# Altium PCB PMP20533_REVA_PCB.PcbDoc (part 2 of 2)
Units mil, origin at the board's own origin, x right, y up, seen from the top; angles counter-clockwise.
Board outline 2795.47 x 1881.89 mil, 4 copper layers (Top Layer, Signal Layer 1, Signal Layer 2, Bottom Layer), stack 40.634 mil thick; 90 components, 59 nets, 312 pads, 73 vias.
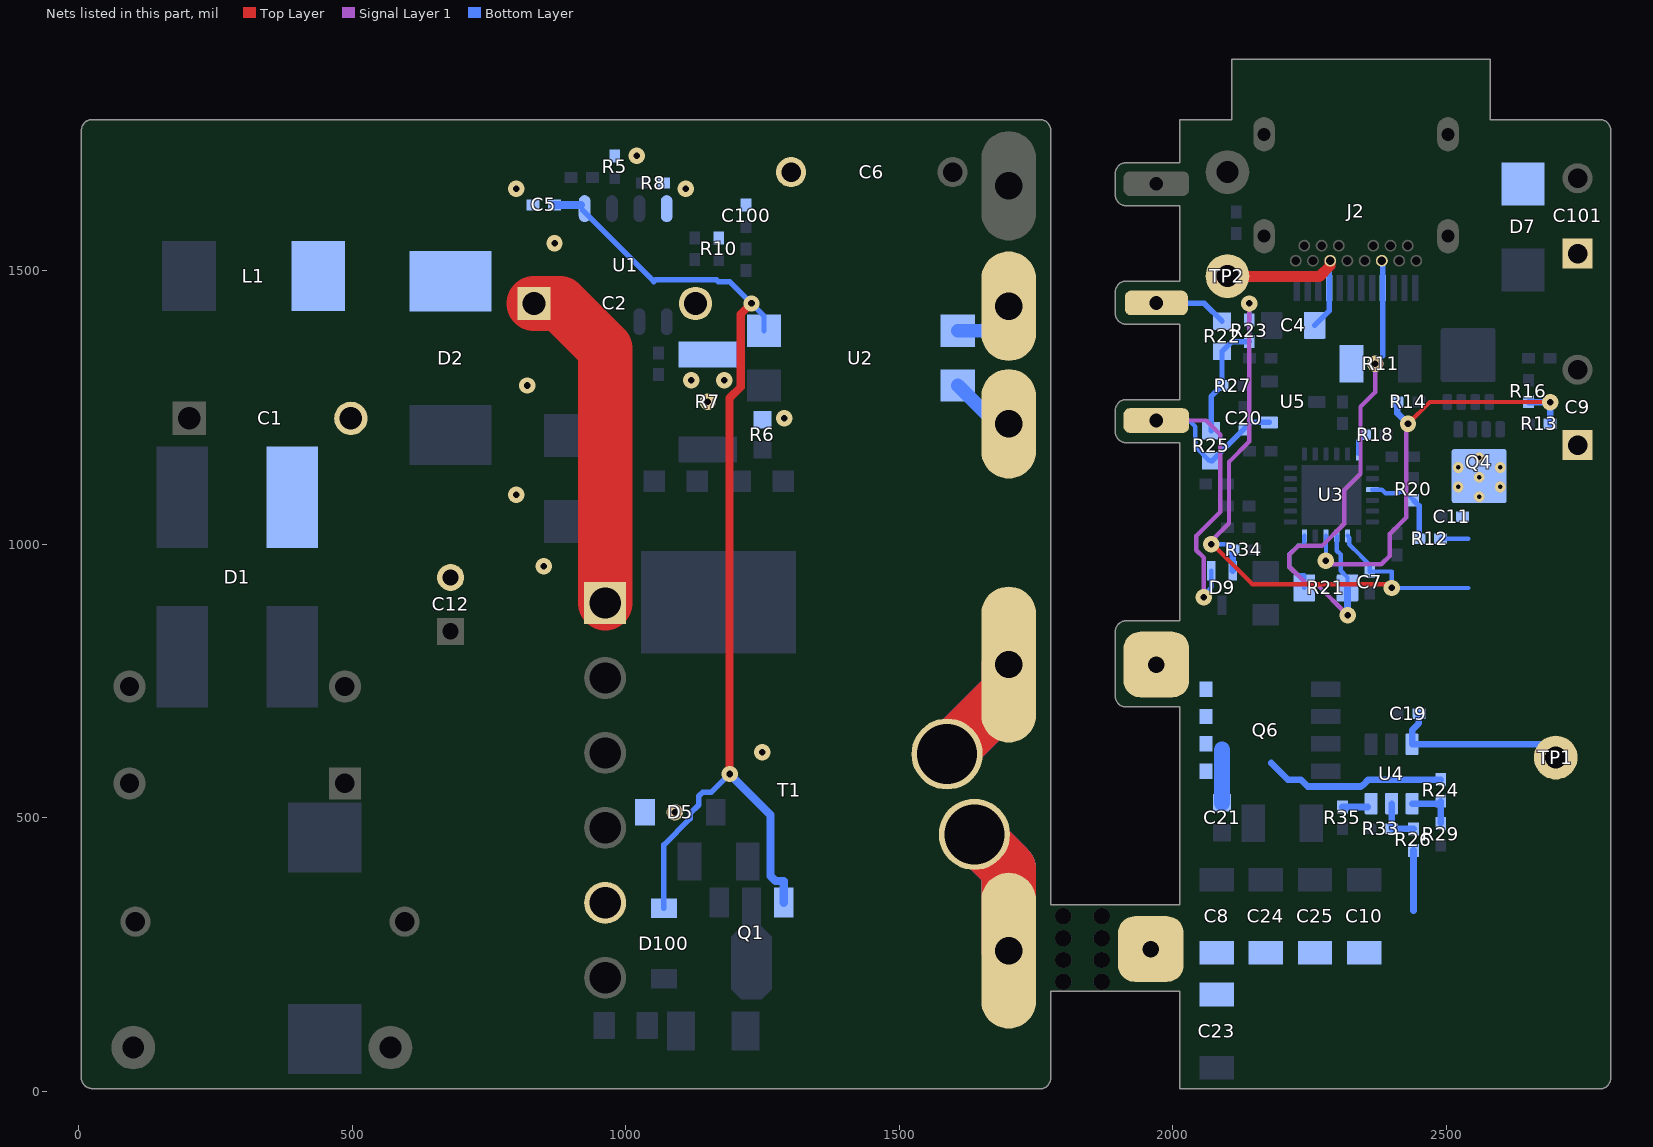
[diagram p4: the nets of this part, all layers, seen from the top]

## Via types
v1: diameter 30, hole 12, Top Layer to Bottom Layer, 54 vias
v2: diameter 19.68, hole 7.87, Top Layer to Bottom Layer, 17 vias
v3: diameter 19.68, hole 7.87, Top Layer to Bottom Layer, tented both sides, 2 vias

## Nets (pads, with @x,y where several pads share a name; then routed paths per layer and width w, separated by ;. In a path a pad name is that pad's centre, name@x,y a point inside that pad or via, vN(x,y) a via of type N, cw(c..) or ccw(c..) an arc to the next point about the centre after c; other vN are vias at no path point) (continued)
NetR12_2: R12.2 R20.2 U3.15 | length 150.4
  Bottom Layer w8: U3.15@2364.8,1099.84 2382.15,1099.84 2388.87,1093.13 2411.13,1093.13 2414.13,1096.13 2424.19,1096.13 R20.2@2440,1080.31
  Bottom Layer w10: R20.2@2440,1080.31 2450.31,1070 2450.31,1020
NetR13_2: R13.2 R14.2 R16.1 U3.22 | length 829
  Top Layer w8: v1(2430,1220) 2469.96,1259.96 v1@2689.41,1259.96
  Signal Layer 1 w8: v1(2280,970) 2286.87,963.13 2381.13,963.13 2396.87,978.87 2396.87,1018.87 2426.87,1048.87 2426.87,1216.87 v1(2430,1220)
  Bottom Layer w8: v1@2280.16,970.16 U3.22@2280.16,1015.2
  Bottom Layer w12: R14.2@2410.31,1260 2410.31,1239.69 v1(2430,1220) ; R16.1@2650.63,1259.69 v1(2689.69,1259.69) R13.2@2689.69,1220
NetR18_2: R18.2 U3.12 | length 39.8
  Bottom Layer w8: U3.12@2339.21,1164.8 2339.21,1188.9 R18.2@2350.31,1200
NetR21_1: R21.1 U3.24 | length 131.8
  Bottom Layer w8: R21.1@2240.63,920 2240.63,943.13 2228.87,943.13 2213.13,958.87 2213.13,981.13 2228.87,996.87 2240.63,996.87 2240.63,1015.04 U3.24@2240.79,1015.2
NetR22_2: R22.2 R23.1 R25.1 R27.2 | length 210.4
  Bottom Layer w10: R25.1@2070,1207.56 2070,1269.69 R27.2@2090.31,1290 ; R27.2@2090,1290.31 R22.2@2090,1352.44 2107.87,1370.32 R23.1@2140,1370.32
NetR24_1: R24.1 R29.2 U4.1 | length 95.1
  Bottom Layer w12: U4.1@2437.4,525.87 2485.55,525.87 R24.1@2490,530.32 R29.2@2490,489.69
NetR26_1: R26.1 R33.2 U4.2 | length 86.2
  Bottom Layer w12: U4.2@2400,525.87 2400,479.68 R26.1@2440,479.68
NetR35_2: R35.2 U4.3 | length 46.4
  Bottom Layer w12: R35.2@2310,519.69 U4.3@2356.42,519.69
PGND: C1.2 C2.2 C5.2 C6.2 C12.2 C100.2 D1.4 D5.2 R5.1 R6.1 R7.1 R8.1 R10.1 T1.5 U1.4
  other v1: 1090,510 1250,620 850,960 800,1090 1290,1230 1150,1260 820,1290 1120,1300 1180,1300 870,1550 800,1650 1110,1650 1020,1710
VBUS: C4.1 D7.1 J2.A4 J2.A9 J2.B4 J2.B9 R11.1 R21.2 TP2.1 U3.21 | length 1262.8
  Top Layer w20: TP2.1@2100,1490 2100,1489.37 2268.14,1489.37 2287.75,1508.98 J2.B9@2287.75,1518.07
  Signal Layer 1 w8: v1(2320,870) 2262.75,927.25 2244.74,927.25 2213.13,958.87 2213.13,981.13 2228.87,996.87 2272.86,996.87 2313.56,1037.57 2313.56,1099 2343.13,1128.56 2343.13,1251.13 2370,1278.01 v1(2370,1330)
  Bottom Layer w8: U3.21@2299.84,1015.2 2299.84,988.16 2306.87,981.13 2306.87,951.67 2319.37,939.17 R21.2@2319.37,920
  Bottom Layer w10: C4.1@2259.37,1400 2285.78,1426.41 J2.A4@2285.78,1468.47 J2.B9@2285.78,1516.1 ; 2384.21,1344.21 J2.A9@2384.21,1468.47 J2.B4@2384.21,1516.1
  Bottom Layer w12: v1@2319.37,870.63 R21.2@2319.37,920
VDC: C2.1 D2.2 L1.2 T1.1 U1.8 | length 668.6
  Top Layer w100: C2.1@832.36,1440 880,1440 962.5,1357.5 T1.1@962.5,892.5
  Bottom Layer w10: 885.71,1406.65 U1.8@925,1406.65
VDD: C5.1 D100.2 Q1.3 U1.1 U2.4 | length 1956
  Top Layer w15: v1(1190,580) 1190,1267.04 1210.37,1287.42 1210.37,1420.37 v1(1230,1440)
  Bottom Layer w10: U1.1@921.65,1610 1051.65,1480 1055.04,1483.39 1165.61,1483.39 1168.99,1480 1190,1480 v1(1230,1440) 1252.83,1417.17 U2.4@1252.83,1390 ; D100.2@1070,334.47 1070,450.58 1117.87,498.45 1117.87,507.87 1133.58,523.58 1133.58,539.35 1141.12,546.89 1156.89,546.89 v1(1190,580)
  Bottom Layer w15: C5.1@869.68,1620 U1.1@918.35,1620 ; v1(1190,580) 1264.63,505.37 1264.63,393.63 1273.63,384.63 1289.06,384.63 Q1.3@1289.06,344.8
VOPTO_1: pad.0@1700,1435 U2.1 | length 111.5
  Bottom Layer w25: U2.1@1607.17,1390 1655,1390 pad.0@1700,1435
VOPTO_1B: pad.2@1970,1441 R22.1 | length 132.4
  Bottom Layer w10: pad.2@1971,1440 2057.56,1440 R22.1@2090,1407.56
VOPTO_2: pad.0@1700,1220 U2.2 | length 121.8
  Bottom Layer w25: U2.2@1607.17,1290 1677.17,1220 pad.0@1700,1220
VOPTO_2B: C20.1 D9.1 pad.2@1970,1226 R25.2 U5.1 | length 790
  Signal Layer 1 w8: pad.2@1970,1226 2061.24,1226 2086.87,1200.37 2086.87,1058.87 2043.13,1015.12 2043.13,988.87 2056.54,975.46 v1(2056.54,903.27)
  Bottom Layer w8: pad.2@1970,1226 2029.84,1226 2041.39,1214.45 2041.39,1177.69 2066.64,1152.44 R25.2@2070,1152.44 ; v1(2056.54,903.27) 2056.54,906.54 2070.32,920.32 D9.1@2070.32,951.5
  Bottom Layer w10: R25.2@2070,1152.44 2072.13,1152.44 C20.1@2130,1210.32 2142.28,1222.6 U5.1@2176.69,1222.6
VOUT_UNFILT: pad.0@1700,257 T1.A | length 476.8
  Top Layer w100: T1.A@1637.5,469.5 1700,407 pad.0@1700,257
  Bottom Layer w100: T1.A@1637.5,469.5 1700,407 pad.0@1700,257
VOUT_UNFILTB: C7.1 C8.1 C9.1 C10.1 C11.1 C19.1 C23.1 C24.1 C25.1 C101.1 D9.2 pad.2@1960,260 Q4.5 Q4.6 Q4.7 Q4.8 Q4.9@2560,1124.41 R12.1 R23.2 R26.2 R34.1 TP1.1 U3.20 U4.6 | length 1729.5
  Top Layer w8: v1@2072.41,1000 2145.54,926.87 2393.13,926.87 v1(2400,920)
  Signal Layer 1 w8: v1(2070,1000) 2070,1005.59 2102.81,1038.4 2102.81,1150.45 2140,1187.64 v1(2140,1440)
  Bottom Layer w8: v1(2070,1000) 2100.32,1000 R34.1@2110.32,990 ; R23.2@2140,1409.69 v1(2140,1440) ; U3.20@2319.53,1015.2 2322.61,1012.11 2322.61,999.63 2343.13,979.12 2343.13,978.87 2358.87,963.13 2360,963.13 C7.1@2360,950 ; C7.1@2360,949.68 C7.1@2360,950 ; R12.1@2489.68,1010 2540,1010 ; 2540,920 v1(2400,920) 2400,950 C7.1@2360,950
  Bottom Layer w12: D9.2@2109.69,951.5 R34.1@2109.69,989.37 ; 2440,330 R26.2@2440,440.31 ; C19.1@2449.68,690 2449.68,672.36 2437.4,660.08 U4.6@2437.4,634.13 2675.87,634.13 TP1.1@2700,610
  other v2: 2521.61,1104.72 2598.39,1104.72 2560,1122.54 2521.61,1140.35 2598.39,1140.35 2560,1158.17
  other v3: 2560,1086.91
VSR_DRAIN: pad.0@1700,780 T1.B | length 420.2
  Top Layer w100: T1.B@1587.5,616.5 1700,729 pad.0@1700,780
  Bottom Layer w100: T1.B@1587.5,616.5 1700,729 pad.0@1700,780
VSR_DRAINB: C21.2 pad.2@1970,780 Q6.5 Q6.6 Q6.7 Q6.8 R24.2 | length 429.5
  Bottom Layer w12: 2180,600 2210.31,569.69 2234.01,569.69 2246.55,557.15 2343.94,557.15 2346.22,559.43 2347.53,559.43 2357.79,569.69 R24.2@2490,569.69
  Bottom Layer w30: C21.2@2090,527.56 2090,624.15
pads on no net: J2.A2 J2.A3 J2.A8 J2.A10 J2.A11 J2.B2 J2.B3 J2.B8 J2.B10 J2.B11 Q4.9@2521.61,1103.74 Q4.9@2533.92,1123.86 Q4.9@2533.92,1158.35 Q4.9@2547.2,1103.74 Q4.9@2560,1137.11 Q4.9@2572.8,1103.74 Q4.9@2586.08,1123.86 Q4.9@2586.08,1158.35 Q4.9@2598.39,1103.74 Q5.9@2501.61,1366.26 Q5.9@2513.92,1311.65 Q5.9@2513.92,1346.14 Q5.9@2527.2,1366.26 Q5.9@2540,1332.89 Q5.9@2552.8,1366.26 Q5.9@2566.08,1311.65 Q5.9@2566.08,1346.14 Q5.9@2578.39,1366.26 T1.2 T1.4 U3.9 U3.10 U3.11 U3.25@2261.85,1061.85 U3.25@2261.85,1118.15 U3.25@2318.15,1061.85 U3.25@2318.15,1118.15

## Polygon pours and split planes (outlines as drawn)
GND on Bottom Layer "BOTTOM_LAYER_GND_P050" (solid, remove dead copper, pour order 50): 1900,1891.31 1900,0 2805.49,0 2805.49,1891.31
VBUS on Bottom Layer "BOTTOM_LAYER_VBUS_P020" (solid, remove dead copper, pour order 20): 2690,1710 2690,1560 2601.02,1560 2601.02,1290 2238.26,1290 2238.26,1710
NetQ5_5 on Bottom Layer "BOTTOM_LAYER_NETQ5_5_P018" (solid, remove dead copper, pour order 18): 2400,1400 2400,1290 2601.02,1290 2601.02,1400
NetQ4_1 on Bottom Layer "BOTTOM_LAYER_NETQ4_1_P016" (solid, remove dead copper, pour order 16): 2606.93,1280 2606.93,1200 2510,1200 2510,1280
VSR_DRAINB on Bottom Layer "BOTTOM_LAYER_VSR_DRAINB_P014" (solid, remove dead copper, pour order 14): 2250,840.24 1910,840.24 1910,550 2250,550
VOUT_UNFILTB on Bottom Layer "BOTTOM_LAYER_VOUT_UNFILTB_P012" (solid, remove dead copper, pour order 12): 2510,1220 2510,4.41 2805.49,4.41 2805.49,1220
VOUT_UNFILTB on Bottom Layer "BOTTOM_LAYER_VOUT_UNFILTB_P010" (solid, remove dead copper, pour order 10): 1900,340 1900,4.41 2530,4.41 2530,340
PGND on Bottom Layer "BOTTOM_LAYER_PGND_P006" (solid, remove dead copper, pour order 6): 0.18,1776.06 0.18,990 650,990 650,900 832.46,900 831.97,4.41 1340,4.41 1340,1776.06
VDC on Bottom Layer "BOTTOM_LAYER_VDC_P004" (solid, remove dead copper, pour order 4): 340,1610 340,1350 890,1350 890,1480 787.58,1480 787.58,1610
NetQ2_2 on Bottom Layer "BOTTOM_LAYER_NETQ2_2_P002" (solid, remove dead copper, pour order 2): 1030,1080 1320,1080 1320,1200 1030,1200
NetD3_2 on Bottom Layer "BOTTOM_LAYER_NETD3_2_P000" (solid, remove dead copper, pour order 0): 1030,1062.5 1030,690 1327.47,690 1327.47,1062.5
GND on Top Layer "TOP_LAYER_GND_P058" (solid, remove dead copper, pour order 58): 1889.95,1886.3 1889.95,4.41 2805.49,4.41 2805.49,1886.3
PGND on Top Layer "TOP_LAYER_PGND_P008" (solid, remove dead copper, pour order 8): 0.18,1776.06 0.18,990 650,990 650,900 832.5,900 832.5,9.42 1340,9.42 1340,1776.06
GND on Signal Layer 2 "SIGNAL_LAYER_2_GND_P052" (solid, remove dead copper, pour order 52): 1900,1886.3 1900,4.41 2799.83,4.41 2799.83,1886.3
GND on Signal Layer 1 "SIGNAL_LAYER_1_GND_P056" (solid, remove dead copper, pour order 56): 1889.95,1886.3 1889.95,9.42 2805.49,9.42 2805.49,1886.3
VSR_DRAINB on Signal Layer 1 "SIGNAL_LAYER_1_VSR_DRAINB_P034" (solid, remove dead copper, pour order 34): 1897.47,859.92 1897.47,710 2018.09,710 2018.09,859.92
VOUT_UNFILTB on Signal Layer 1 "SIGNAL_LAYER_1_VOUT_UNFILTB_P054" (solid, remove dead copper, pour order 54): 2800.47,1070 2502.13,1070 2502.13,1570 2800.47,1570

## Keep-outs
Keep-Out Layer:
  rectangle: 1280,400 1500,766.06
  rectangle: 1340,730 1560,1776.06
  rectangle: 1340,10 1560,520
  lines w5: 2.5,25 ccw(c25,25) 25,2.5 ; 2.5,25 ccw(c5,25) 2.5,25 ; 2.5,25 ccw(c5,25) 2.5,25 ; 2.5,25 2.7,1756.38 ; 2.7,1756.38 cw(c24.88,1756.38) 24.88,1778.56 ; 2.7,1756.38 ccw(c24.88,1756.38) 2.7,1756.38 ; 2.7,1756.38 2.7,1756.38 ; 24.9,1778.56 ccw(c24.88,1776.06) 24.88,1778.56 ; 24.9,1778.56 ccw(c24.88,1776.06) 24.88,1778.56 ; 24.88,1778.56 24.9,1778.56 ; 24.9,1778.56 1757.14,1778.56 ; 25,2.5 ccw(c25,25) 25,2.5 ; 25,2.5 25,2.5 ; 25,2.5 1757.16,1.91 ; 1757.16,1.91 ccw(c1757.17,4.41) 1757.17,1.91 ; 1757.16,1.91 ccw(c1757.17,4.41) 1757.17,1.91 ; 1757.17,1.91 ccw(c1757.17,24.09) 1779.35,24.09 1779.35,180.65 2010.57,180.65 2010.57,4.41 ; 1757.17,1778.56 cw(c1757.17,1756.38) 1779.35,1756.38 1779.35,343.13 2010.57,343.13 2010.57,699.94 1914.65,699.94 cw(c1914.65,722.13) 1892.46,722.13 1892.46,840.24 cw(c1914.65,840.24) 1914.65,862.42 2010.57,862.42 2010.57,1183.01 1914.67,1183.01 ; 1757.17,1778.56 ccw(c1757.17,1776.06) 1757.14,1778.56 ; 1757.17,1778.56 ccw(c1757.17,1776.06) 1757.14,1778.56 ; 1757.14,1778.56 1757.17,1778.56 ; 1892.46,1244.57 ccw(c1894.96,1244.57) 1892.46,1244.54 ; 1892.46,1244.57 ccw(c1894.96,1244.57) 1892.46,1244.54 ; 1892.46,1244.57 cw(c1914.65,1244.57) 1914.65,1266.75 2010.57,1266.75 2010.57,1399.55 1914.67,1399.55 ; 1892.46,1244.54 1892.46,1205.2 ccw(c1914.65,1205.2) 1914.65,1183.01 ; 1892.46,1244.54 1892.46,1244.57 ; 1892.46,1461.1 ccw(c1894.96,1461.1) 1892.46,1461.08 ; 1892.46,1461.1 ccw(c1894.96,1461.1) 1892.46,1461.08 ; 1892.46,1461.1 cw(c1914.65,1461.1) 1914.62,1483.29 ; 1892.46,1461.08 1892.46,1421.73 ccw(c1914.65,1421.73) 1914.65,1399.55 ; 1892.46,1461.08 1892.46,1461.1 ; 1892.46,1677.62 cw(c1894.96,1677.64) 1892.46,1677.64 ; 1892.46,1677.62 cw(c1894.96,1677.64) 1892.46,1677.64 ; 1892.46,1677.62 1892.46,1638.27 ccw(c1914.65,1638.27) 1914.65,1616.08 ; 1892.46,1677.62 1892.46,1677.64 ; 1892.46,1677.64 cw(c1914.65,1677.64) 1914.65,1699.82 2010.57,1699.82 2010.57,1776.06 ; 1914.62,1483.29 cw(c1914.65,1461.1) 1914.65,1483.29 ; 1914.62,1483.29 cw(c1914.65,1480.79) 1914.65,1483.29 ; 1914.62,1483.29 cw(c1914.65,1480.79) 1914.65,1483.29 ; 1914.65,1183.01 ccw(c1914.65,1185.51) 1914.67,1183.01 ; 1914.65,1183.01 ccw(c1914.65,1185.51) 1914.67,1183.01 ; 1914.65,1183.01 1914.67,1183.01 ; 1914.65,1399.55 ccw(c1914.65,1402.05) 1914.67,1399.55 ; 1914.65,1399.55 ccw(c1914.65,1402.05) 1914.67,1399.55 ; 1914.65,1399.55 1914.67,1399.55 ; 1914.65,1483.29 2010.57,1483.29 2010.57,1616.08 1914.67,1616.08 ; 1914.65,1616.08 ccw(c1914.65,1618.58) 1914.67,1616.08 ; 1914.65,1616.08 ccw(c1914.65,1618.58) 1914.67,1616.08 ; 1914.65,1616.08 1914.67,1616.08 ; 2010.57,4.41 ccw(c2013.07,4.41) 2013.07,1.91 ; 2010.57,4.41 ccw(c2013.07,4.41) 2013.07,1.91 ; 2010.57,1776.06 cw(c2013.07,1776.06) 2013.07,1778.56 ; 2010.57,1776.06 cw(c2013.07,1776.06) 2013.07,1778.56 ; 2013.07,1.91 2780.79,1.91 ccw(c2780.79,24.09) 2802.97,24.07 ; 2013.07,1778.56 2105.06,1778.56 2105.06,1886.3 ; 2105.06,1886.3 cw(c2107.56,1886.3) 2107.56,1888.8 ; 2105.06,1886.3 cw(c2107.56,1886.3) 2107.56,1888.8 ; 2107.56,1888.8 2580,1888.8 ; 2580,1888.8 cw(c2580,1886.3) 2582.5,1886.3 ; 2580,1888.8 cw(c2580,1886.3) 2582.5,1886.3 ; 2582.5,1886.3 2582.5,1778.56 2780.76,1778.56 ; 2780.76,1778.56 cw(c2780.79,1776.06) 2780.79,1778.56 ; 2780.76,1778.56 cw(c2780.79,1776.06) 2780.79,1778.56 ; 2780.76,1778.56 2780.79,1778.56 ; 2780.79,1778.56 cw(c2780.79,1756.38) 2802.97,1756.4 ; 2802.97,24.07 ccw(c2800.47,24.09) 2802.97,24.09 ; 2802.97,24.07 ccw(c2780.79,24.09) 2802.97,24.09 ; 2802.97,24.07 ccw(c2800.47,24.09) 2802.97,24.09 ; 2802.97,24.09 2802.97,1756.38 ; 2802.97,1756.38 ccw(c2800.47,1756.38) 2802.97,1756.4 ; 2802.97,1756.38 ccw(c2800.47,1756.38) 2802.97,1756.4 ; 2802.97,1756.38 ccw(c2780.79,1756.38) 2802.97,1756.4
  text ".Layer_Name" at 577,-858.49 h60

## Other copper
Top Layer:
  text ".Layer_Name" at 577,-858.49 h60
Bottom Layer:
  text ".Layer_Name" at 577,-858.49 h60

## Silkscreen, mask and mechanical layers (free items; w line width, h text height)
Top Overlay:
  text ".Layer_Name" at 577,-858.49 h60
Bottom Overlay:
  region: 1600,50 1600,400 1500,400 1500,50
  text "PMP20533PCB Rev A" at 1470,1020 h108.27 r90
  text ".Layer_Name" at 577,-858.49 h60
Top Paste:
  text ".Layer_Name" at 577,-858.49 h60
Bottom Paste:
  text ".Layer_Name" at 577,-858.49 h60
Top Solder:
  text ".Layer_Name" at 577,-858.49 h60
  text ".Layer_Name" at 577,-858.49 h60
Bottom Solder:
  text ".Layer_Name" at 577,-858.49 h60
Drill Guide:
  text ".Layer_Name" at 577,-858.49 h60
M1 Board Outline:
  the board outline again, w10
  text ".Layer_Name" at 577,-858.49 h60
M2 Board Dimensions:
  rectangle: 125,-400 500,-275
  rectangle: 0,-275 125,-150
  lines w7: 0,-275 1000,-275 ; 125,-400 125,-150 ; 250,-400 250,-150 ; 500,-400 500,-150 ; 750,-400 750,-150 ; 0,-400 0,-150 1000,-150 1000,-400 0,-400
  text ".Layer_Name" at 577,-858.49 h60
M3 3D STEP Top:
  text ".Layer_Name" at 577,-858.49 h60
M4 3D STEP Bottom:
  text ".Layer_Name" at 577,-858.49 h60
M5 Assembly Top:
  lines w10: -292,-930.17 6308,-930.17 ; -292,-726.83 6310,-726.83 ; -292,-523.5 -292,-1133.5 3713,-1133.5 6310,-1133.5 6310,-523.5 -291.5,-523.5 -291.5,-1133.5 1284,-1133.5 ; 2173,-1133.5 2173,-523.5 ; 3440,-726.83 3440,-523.5 ; 4280,-726.83 4280,-523.5 ; 4902,-1140 4902,-937.17
  text "COMPONENTS MARKED 'DNP' SHOULD NOT BE POPULATED." at 1153.5,-318.5 h60
  text "ASSEMBLY VARIANT:" at 1153,-434 h60
  text ".VariantName" at 2189,-434 h60
  text "PCB VIEWED FROM TOP SIDE" at -228.5,-655.67 h60
  text "BOARD #:" at 2248,-655.67 h60
  text ".PRJ_Number" at 2793.5,-655.67 h60
  text "REV:" at 3638,-655.67 h60
  text ".PCB_Rev" at 3929.5,-655.67 h60
  text "SVN REV:" at 4476,-655.67 h60
  text ".VersionControl_RevNumber" at 4982,-655.67 h60
  text "TID #:" at 2248,-859 h60
  text ".TID" at 2793.5,-859 h60
  text "PLOT NAME =" at -228.5,-1064.34 h60
  text ".plot_File_Name" at 577,-1064.34 h60
  text "GENERATED    :" at 2250,-1064.34 h60
  text ".Print_Date" at 3119.5,-1064.34 h60
  text ".Print_Time" at 3848.5,-1064.34 h60
  text "TEXAS INSTRUMENTS" at 5113,-1064.34 h60
M6 Assembly Bottom:
  lines w10: -292.5,-727.33 6309.5,-727.33 ; -290.5,-930.67 6309.5,-930.67 ; 1115.5,-1140.5 1115.5,-937.67 ; 1737.5,-727.33 1737.5,-524 ; 2577.5,-727.33 2577.5,-524 ; 3844.5,-1134 3844.5,-524 ; 4733.5,-1134 6309,-1134 6309,-524 -292.5,-524 -292.5,-1134 2304.5,-1134 6309.5,-1134 6309.5,-524
  text "COMPONENTS MARKED 'DNP' SHOULD NOT BE POPULATED." at 6102,-318 h60
  text ".VariantName" at 5058,-434 h60
  text "ASSEMBLY VARIANT:" at 6097,-434 h60
  text ".VersionControl_RevNumber" at 1035.5,-656.17 h60
  text "SVN REV:" at 1541.5,-656.17 h60
  text ".PCB_Rev" at 2088,-656.17 h60
  text "REV:" at 2379.5,-656.17 h60
  text ".PRJ_Number" at 3224,-656.17 h60
  text "BOARD #:" at 3769.5,-656.17 h60
  text "PCB VIEWED FROM BOTTOM SIDE" at 6246,-656.17 h60
  text ".TID" at 3224,-859.5 h60
  text "TID #:" at 3769.5,-859.5 h60
  text "TEXAS INSTRUMENTS" at 904.5,-1064.84 h60
  text ".Print_Time" at 2169,-1064.84 h60
  text ".Print_Date" at 2898,-1064.84 h60
  text "GENERATED    :" at 3767.5,-1064.84 h60
  text ".plot_File_Name" at 5440.5,-1064.84 h60
  text "PLOT NAME =" at 6246,-1064.84 h60
M9 Title Sheet:
  drawing of 57 lines, arcs and shapes, not listed
  text "1" at 739.84,8036.5 h70
  text "2" at 3235.5,8036.5 h70
  text "3" at 5724.84,8036.5 h70
  text "4" at 8231.51,8036.5 h70
  text "5" at 10730.5,8036.5 h70
  text "6" at 13235.5,8036.5 h70
  text "A" at -416.5,6893.5 h70
  text "A" at 14383.5,6893.5 h70
  text "B" at -416.5,4513.5 h70
  text "B" at 14383.5,4513.5 h70
  text "C" at -416.5,2138.5 h70
  text "C" at 14383.5,2138.5 h70
  text "PROJECT TITLE:" at 11343.5,277.5 h45
  text ".PRJ_Title" at 11393.5,144.17 h70
  text "DESIGNED FOR:" at 11343.5,-23.5 h45
  text ".PRJ_Customer" at 11393.5,-163.5 h70
  text "D" at -416.5,-231.5 h70
  text "D" at 14383.5,-231.5 h70
  text "FILE NAME:" at 11343.5,-323.5 h45
  text ".PCB_File_Name_No_Path" at 11393.5,-443.5 h70
  text "Texas Instruments (TI) and/or its licensors do not warrant the accuracy or completeness of this specification" at 6374,-605.34 h45
  text "ENGINEER:" at 11343.5,-613.5 h45
  text "LAYOUT BY:" at 12848.5,-613.5 h45
  text "or any information contained therein. TI and/or its licensors do not warrant that this design will meet" at 6329.01,-718 h45
  text ".PRJ_Engineer" at 11393.5,-768.49 h70
  text ".PCB_Layout" at 12899,-768.49 h70
  text "the specifications, will be suitable for your application or fit for any particular purpose, or will operate in" at 6329.01,-830.67 h45
  text ".Layer_Name" at 577,-858.49 h60
  text "ALTIUM DESIGNER VERSION:" at 12848.5,-923.5 h45
  text "an implementation. TI and/or its licensors do not warrant that the design is production worthy. You should" at 6329.01,-943.33 h45
  text "completely validate and test your design implementation to confirm the system functionality for your application." at 6374,-1056 h45
  text ".print_Scale" at 11393.5,-1056.83 h70
  text ".Application_BuildNumber" at 12899,-1056.83 h70
  text "1" at 739.84,-1263.5 h70
  text "2" at 3235.5,-1263.5 h70
  text "3" at 5724.84,-1263.5 h70
  text "4" at 8231.51,-1263.5 h70
  text "5" at 10730.5,-1263.5 h70
  text "6" at 13235.5,-1263.5 h70
M10 Fab Notes:
  drawing of 173 lines, arcs and shapes, not listed
  text "DESIGN INFORMATION" at 12378.02,6201 h60
  text "MIN. TRACK WIDTH:" at 11733.46,6021 h60
  text "8" at 12829.7,6021 h60
  text "MIL" at 12984.46,6021 h60
  text "MIN. CLEARANCE:" at 11733.46,5889 h60
  text "0.2" at 12769.7,5889 h60
  text "mm" at 12984.46,5889 h60
  text "MIN. VIA PAD SIZE:" at 11733.46,5757 h60
  text "24" at 12799.71,5757 h60
  text "MIL" at 12984.46,5757 h60
  text "0.05mm (2MIL)" at 12428.46,5615.29 h60
  text "MINIMUM ANNULAR RING" at 11404.23,5611 h60
  text "EXTERNAL" at 13136.46,5611 h60
  text "PER" at 11604.23,5493 h60
  text "IPC-D-275 CLASS 2 LEVEL C" at 11824.23,5493 h60
  text "MIL, HOLES" at 13312.46,5380.71 h60
  text "+/-" at 12920,5380 h60
  text "+/-" at 13774,5380 h60
  text "REGISTRATION TOLERANCES:" at 11404.23,5375 h60
  text "METAL" at 12604,5375 h60
  text "5" at 13180.2,5375 h60
  text "3" at 14013.2,5375 h60
  text "MIL" at 14129.46,5375 h60
  text "+/-" at 13774,5262 h60
  text "HOLE SIZE TOLERANCE (UNLESS OTHERWISE SPECIFIED):" at 11404.23,5257 h60
  text "3" at 14013.2,5257 h60
  text "MIL" at 14129.46,5257 h60
  text "MATERIAL:" at 11329.46,5047.54 h60
  text "FR-4 High Tg" at 12315.9,4907.21 h60
  text "FR-408" at 11750.46,4898.64 h60
  text "OTHER" at 13238.46,4898.64 h60
  text "X" at 12161,4895 h60
  text "X" at 13240,4750 h60
  text "39MIL" at 13670,4750 h60
  text "62 MIL (1.6mm) +/-10%" at 12070.56,4735.92 h60
  text "THICKNESS:" at 11404.23,4731.64 h60
  text "OTHER" at 13355.46,4731.64 h60
  text "TOLERANCE:" at 11404.23,4573.64 h60
  text "X" at 12243.53,4573.64 h60
  text "ANSI IPC-6012 TYPE 3 CLASS 2" at 12430.48,4573.64 h60
  text "OTHER +/-" at 12430.46,4417.64 h60
  text "BOW & TWIST:" at 11404.23,4260.64 h60
  text "X" at 12243.53,4260.64 h60
  text "ANSI IPC-6012 TYPE 3 CLASS 2" at 12430.48,4260.64 h60
  text "OTHER +/-" at 12430.46,4102.13 h60
  text "DRILLING:" at 11329.46,3963.64 h60
  text "REFERENCE:" at 11404.23,3846.64 h60
  text "X" at 12052.46,3846.64 h60
  text "AS SHOWN" at 12239.46,3846.64 h60
  text "X" at 12953.46,3846.64 h60
  text "NC_DRILL FILES" at 13090.46,3846.64 h60
  text "PTH COPPER THICKNESS:" at 11404.23,3688.64 h60
  text "X" at 12534.46,3688.64 h60
  text "20-30 um" at 12671.46,3688.64 h60
  text "OTHER" at 13388.46,3688.64 h60
  text "BOARD FINISH:" at 11329.46,3529.64 h60
  text "SILKSCREEN:" at 11484.68,3411.64 h60
  text "X" at 12433.46,3411.64 h60
  text "TOP" at 12559.46,3411.64 h60
  text "X" at 12943.46,3411.64 h60
  text "BOTTOM" at 13070.46,3411.64 h60
  text "SILKSCREEN COLOR:" at 11484.68,3244.64 h60
  text "X" at 12432.42,3244.64 h60
  text "WHITE" at 12559.46,3244.64 h60
  text "OTHER" at 13070.46,3244.64 h60
  text "X" at 12563.42,3085.44 h60
  text "GREEN" at 12690.46,3085.44 h60
  text "OTHER" at 13308.46,3085.44 h60
  text "SOLDER RESIST COLOR:" at 11484.68,3074.64 h60
  text "X" at 12563.42,2915.44 h60
  text "MATTE" at 12690.46,2915.44 h60
  text "SEMI-GLOSS" at 13308,2914.8 h60
  text "IMMERSION GOLD (ENIG)" at 12390.46,2726.92 h60
  text "ENEPIG" at 13728,2723.64 h60
  text "SURFACE FINISH:" at 11329.46,2722.64 h60
  text "X" at 12203.51,2722.64 h60
  text "IMM. TIN/SILVER OR EQUIV" at 11659,2565.64 h60
  text "OTHER" at 13090.46,2565.64 h60
  text "ARRAY/PANEL:" at 11329.46,2386.64 h60
  text "CUT AND TRIM PER M1 BOARD OUTLINE" at 12390.46,2382.35 h60
  text "N.C. ROUTE" at 12390.46,2230.64 h60
  text "X" at 13069.46,2230.64 h60
  text "V. SCORE" at 13256.46,2230.64 h60
  text "CERTIFICATION:" at 11329.46,2093.64 h60
  text "MATERIALS AND WORKMANSHIP FOR ALL PCBS" at 12054.46,2093.64 h60
  text "TO MEET OR EXCEED THE REQUIREMENTS OF:" at 12054.46,1995.64 h60
  text "X" at 11680.96,1859.13 h60
  text "ANSI IPC-A-600F CLASS ->" at 11819.96,1859.13 h60
  text "X" at 13459.02,1859.13 h60
  text "2" at 13577.96,1859.14 h60
  text "1" at 13262.96,1857.64 h60
  text "3" at 13931.96,1857.64 h60
  text "X" at 12495.02,1699.64 h60
  text "RoHS" at 12631.96,1699.64 h60
  text "OTHER" at 13276.36,1699.64 h60
  text "PER ORDER" at 13673.42,1699.64 h60
  text "ALL BOARDS MUST MEET OR EXCEED UL94-V0 REQUIREMENTS." at 11357,1534 h60
  text "PCB MUST BEAR THE UL94V-0 UL REGISTERED MATERIAL ID NUMBER" at 11357,1414 h60
  text "ADDITIONAL REQUIREMENTS:" at 11329.46,1240.64 h60
  text "MICROSECTION:" at 11404.23,1125.64 h60
  text "YES" at 12309.96,1125.64 h60
  text "REQUIRED" at 13171.46,969.49 h60
  text "BARE BOARD ELEC. TEST:" at 11404.23,966.64 h60
  text "NONE" at 12709.96,966.64 h60
  text "X" at 13044.46,966.64 h60
  text "PER ORDER" at 13763.46,966.64 h60
  text ".Layer_Name" at 577,-858.49 h60
M11 Gerber Information:
  lines w10: -292,-930.17 6308,-930.17 ; -292,-726.83 6310,-726.83 ; -292,-523.5 -292,-1133.5 3713,-1133.5 6310,-1133.5 6310,-523.5 -291.5,-523.5 -291.5,-1133.5 1284,-1133.5 ; 2173,-1133.5 2173,-523.5 ; 3440,-726.83 3440,-523.5 ; 4280,-726.83 4280,-523.5 ; 4902,-1140 4902,-937.17
  text "ALL ARTWORK VIEWED FROM TOP SIDE" at -228.5,-655.67 h60
  text "BOARD #:" at 2248,-655.67 h60
  text ".PRJ_Number" at 2793.5,-655.67 h60
  text "REV:" at 3638,-655.67 h60
  text ".PCB_Rev" at 3929.5,-655.67 h60
  text "SVN REV:" at 4476,-655.67 h60
  text ".VersionControl_RevNumber" at 4982,-655.67 h60
  text "LAYER NAME =" at -228.5,-858.49 h60
  text "TID #:" at 2248,-859 h60
  text ".TID" at 2793.5,-859 h60
  text "PLOT NAME =" at -228.5,-1064.34 h60
  text ".plot_File_Name" at 577,-1064.34 h60
  text "GENERATED    :" at 2250,-1064.34 h60
  text ".Print_Date" at 3119.5,-1064.34 h60
  text ".Print_Time" at 3848.5,-1064.34 h60
  text "TEXAS INSTRUMENTS" at 5113,-1064.34 h60
M12 Stackup:
  drawing of 295 lines, arcs and shapes, not listed
  text "Layer" at 9720.58,7790 h60
  text "Name" at 10130.49,7790 h60
  text "Material" at 11070.23,7790 h60
  text "Thickness" at 11930,7790 h60
  text "Constant" at 12579.84,7790 h60
  text "Board Layer Stack" at 13149.7,7790 h60
  text "1" at 9720.58,7670 h60
  text "Top Overlay" at 10130.49,7670 h60
  text "2" at 9720.58,7550 h60
  text "Top Solder" at 10130.49,7550 h60
  text "Solder Resist" at 11070.23,7550 h60
  text "0.40mil" at 11930,7550 h60
  text "3.5" at 12579.84,7550 h60
  text "3" at 9720.58,7430 h60
  text "Top Layer" at 10130.49,7430 h60
  text "Copper" at 11070.23,7430 h60
  text "1.40mil" at 11930,7430 h60
  text "4" at 9720.58,7310 h60
  text "Dielectric1" at 10130.49,7310 h60
  text "FR-4" at 11070.23,7310 h60
  text "15.00mil" at 11930,7310 h60
  text "4.8" at 12579.84,7310 h60
  text "5" at 9720.58,7190 h60
  text "Signal Layer 1" at 10130.49,7190 h60
  text "Copper" at 11070.23,7190 h60
  text "1.42mil" at 11930,7190 h60
  text "6" at 9720.58,7070 h60
  text "Dielectric 3" at 10130.49,7070 h60
  text "5.00mil" at 11930,7070 h60
  text "4.2" at 12579.84,7070 h60
  text "7" at 9720.58,6950 h60
  text "Signal Layer 2" at 10130.49,6950 h60
  text "Copper" at 11070.23,6950 h60
  text "1.42mil" at 11930,6950 h60
  text "8" at 9720.58,6830 h60
  text "Dielectric 2" at 10130.49,6830 h60
  text "15.00mil" at 11930,6830 h60
  text "4.2" at 12579.84,6830 h60
  text "9" at 9720.58,6710 h60
  text "Bottom Layer" at 10130.49,6710 h60
  text "Copper" at 11070.23,6710 h60
  text "1.40mil" at 11930,6710 h60
  text "10" at 9720.58,6590 h60
  text "Bottom Solder" at 10130.49,6590 h60
  text "Solder Resist" at 11070.23,6590 h60
  text "0.40mil" at 11930,6590 h60
  text "3.5" at 12579.84,6590 h60
  text "11" at 9720.58,6470 h60
  text "Bottom Overlay" at 10130.49,6470 h60
  text ".Layer_Name" at 577,-858.49 h60
M13 Component Bodies Top:
  text ".Layer_Name" at 577,-858.49 h60
M14 Component Bodies Bottom:
  text ".Layer_Name" at 577,-858.49 h60
M15 Courtyards Top:
  text ".Layer_Name" at 577,-858.49 h60
M16 Courtyards Bottom:
  text ".Layer_Name" at 577,-858.49 h60
Drill Drawing:
  drawing of 162 lines, arcs and shapes, not listed
  text "Symbol" at 5360.59,3368.3 h72
  text "Quantity" at 5661.16,3368.3 h72
  text "Finished Hole Size" at 5993.16,3368.3 h72
  text "Plated" at 6629.72,3368.3 h72
  text "Hole Type" at 6888.86,3368.3 h72
  text "Drill Layer Pair" at 7264.02,3368.3 h72
  text "Hole Tolerance" at 7988.35,3368.3 h72
  text "8" at 5661.16,3243.98 h60
  text "30.00mil (0.762mm)" at 5993.16,3243.98 h60
  text "NPTH" at 6629.72,3243.98 h60
  text "Round" at 6888.86,3243.98 h60
  text "Top Layer - Bottom Layer" at 7264.02,3243.98 h60
  text "19" at 5661.16,3119.66 h60
  text "7.87mil (0.200mm)" at 5993.16,3119.66 h60
  text "PTH" at 6629.72,3119.66 h60
  text "Round" at 6888.86,3119.66 h60
  text "Top Layer - Bottom Layer" at 7264.02,3119.66 h60
  text "54" at 5661.16,2995.34 h60
  text "12.00mil (0.305mm)" at 5993.16,2995.34 h60
  text "PTH" at 6629.72,2995.34 h60
  text "Round" at 6888.86,2995.34 h60
  text "Top Layer - Bottom Layer" at 7264.02,2995.34 h60
  text "14" at 5661.16,2871.02 h60
  text "15.75mil (0.400mm)" at 5993.16,2871.02 h60
  text "PTH" at 6629.72,2871.02 h60
  text "Round" at 6888.86,2871.02 h60
  text "Top Layer - Bottom Layer" at 7264.02,2871.02 h60
  text "3" at 5661.16,2746.7 h60
  text "25.00mil (0.635mm)" at 5993.16,2746.7 h60
  text "PTH" at 6629.72,2746.7 h60
  text "Round" at 6888.86,2746.7 h60
  text "Top Layer - Bottom Layer" at 7264.02,2746.7 h60
  text "2" at 5661.16,2622.38 h60
  text "29.53mil (0.750mm)" at 5993.16,2622.38 h60
  text "PTH" at 6629.72,2622.38 h60
  text "Round" at 6888.86,2622.38 h60
  text "Top Layer - Bottom Layer" at 7264.02,2622.38 h60
  text "2" at 5661.16,2498.06 h60
  text "30.00mil (0.762mm)" at 5993.16,2498.06 h60
  text "PTH" at 6629.72,2498.06 h60
  text "Round" at 6888.86,2498.06 h60
  text "Top Layer - Bottom Layer" at 7264.02,2498.06 h60
  text "12" at 5661.16,2373.74 h60
  text "35.43mil (0.900mm)" at 5993.16,2373.74 h60
  text "PTH" at 6629.72,2373.74 h60
  text "Round" at 6888.86,2373.74 h60
  text "Top Layer - Bottom Layer" at 7264.02,2373.74 h60
  text "5" at 5661.16,2249.42 h60
  text "40.00mil (1.016mm)" at 5993.16,2249.42 h60
  text "PTH" at 6629.72,2249.42 h60
  text "Round" at 6888.86,2249.42 h60
  text "Top Layer - Bottom Layer" at 7264.02,2249.42 h60
  text "4" at 5661.16,2125.1 h60
  text "41.34mil (1.050mm)" at 5993.16,2125.1 h60
  text "PTH" at 6629.72,2125.1 h60
  text "Round" at 6888.86,2125.1 h60
  text "Top Layer - Bottom Layer" at 7264.02,2125.1 h60
  text "6" at 5661.16,2000.78 h60
  text "57.09mil (1.450mm)" at 5993.16,2000.78 h60
  text "PTH" at 6629.72,2000.78 h60
  text "Round" at 6888.86,2000.78 h60
  text "Top Layer - Bottom Layer" at 7264.02,2000.78 h60
  text "B" at 5335.31,1990.79 h55.25
  text "2" at 5661.16,1876.46 h60
  text "110.24mil (2.800mm)" at 5993.16,1876.46 h60
  text "PTH" at 6629.72,1876.46 h60
  text "Round" at 6888.86,1876.46 h60
  text "Top Layer - Bottom Layer" at 7264.02,1876.46 h60
  text "A" at 5335.31,1866.47 h55.25
  text "4" at 5661.16,1752.14 h60
  text "23.62mil (0.600mm)" at 5993.16,1752.14 h60
  text "PTH" at 6629.72,1752.14 h60
  text "Slot" at 6888.86,1752.14 h60
  text "Top Layer - Bottom Layer" at 7264.02,1752.14 h60
  text "3" at 5661.16,1627.82 h60
  text "50.00mil (1.270mm)" at 5993.16,1627.82 h60
  text "PTH" at 6629.72,1627.82 h60
  text "Slot" at 6888.86,1627.82 h60
  text "Top Layer - Bottom Layer" at 7264.02,1627.82 h60
  text "C" at 5335.31,1617.83 h55.25
  text "2" at 5661.16,1503.5 h60
  text "50.00mil (1.270mm)" at 5993.16,1503.5 h60
  text "PTH" at 6629.72,1503.5 h60
  text "Slot" at 6888.86,1503.5 h60
  text "Top Layer - Bottom Layer" at 7264.02,1503.5 h60
  text "140 Total" at 5661.16,1379.18 h60
  text "Slot definitions :" at 5360.59,1292.15 h60
  text "Routed Path Length" at 5811.31,1292.15 h60
  text "= Calculated from tool start centre position to tool end centre position." at 6351.05,1292.15 h60
  text "Hole Length" at 5811.31,1242.43 h60
  text "= Routed Path Length + Tool Size = Slot length as defined in the PCB layout" at 6151.24,1242.43 h60
  text ".Layer_Name" at 577,-858.49 h60
M17 Embedded Cavity:
  text ".Layer_Name" at 577,-858.49 h60
M18 Embedded Assembly:
  text ".Layer_Name" at 577,-858.49 h60
M19 Embedded Keepout:
  text ".Layer_Name" at 577,-858.49 h60

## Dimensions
0,0 to 1780,0 on M2 Board Dimensions
0,-400 to 1000,-400 on M2 Board Dimensions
